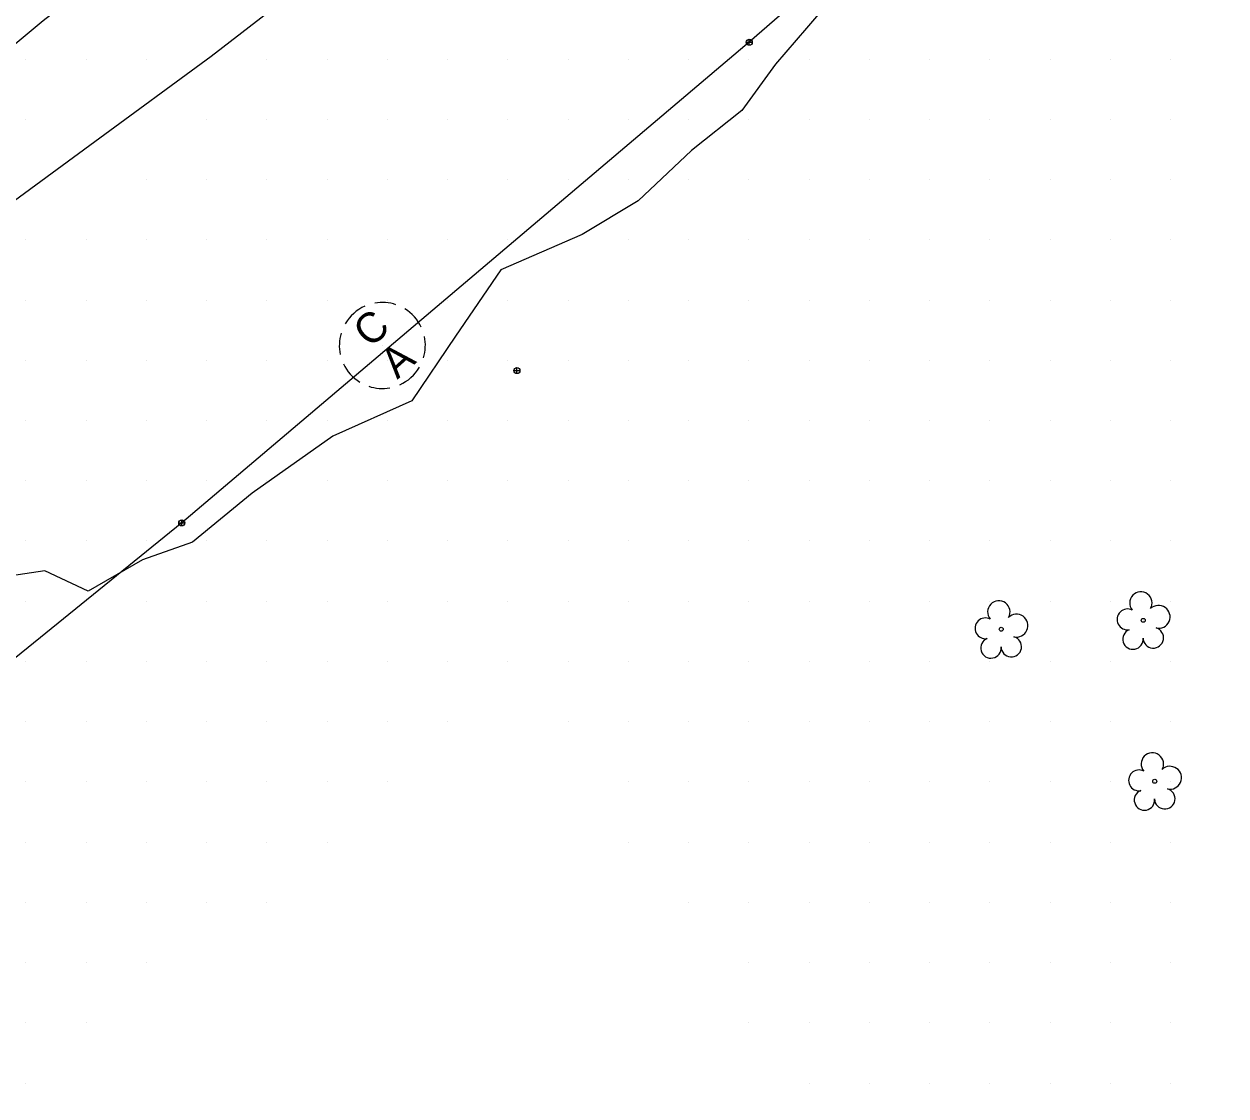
# Model space of a CAD drawing. Extents: x 1548934 to 1561348, y 809680 to 824075.
# Drawn here: x 1551639.7 to 1551839.2, y 810277.8 to 810455.8 of the extents above; entities that cross this region are included whole.
import ezdxf

# ---------------------------------------------------------------- set-up
doc = ezdxf.new("R2010")
doc.units = 0
for name, color, linetype in [('Default', 7, 'Continuous'), ('Exist DTM QL2 LIDAR Elevation Point', 7, 'Continuous'), ('Exist Right of Way Control of Access CA Symbol CELL', 7, 'Continuous'), ('Exist Vegetation Tree CELL', 7, 'Continuous'), ('Exist Vegetation Woods Line', 7, 'Continuous'), ('P_RDY_Dimension_Text', 7, 'Continuous'), ('PH Exist DTM Breakline', 7, 'Continuous')]:
    doc.layers.add(name, color=color, linetype=linetype)

# ---------------------------------------------------------------- blocks, each defined once
blk = doc.blocks.new('SurveyPointCell')
at = {"layer": 'Default'}
for p, q in [((-0.5, 0), (0.5, 0)), ((0, -0.5), (0, 0.5))]:
    blk.add_line(p, q, dxfattribs=at)
blk.add_circle((0, 0), 0.5, dxfattribs=at)

msp = doc.modelspace()

# ---------------------------------------------------------------- linework, layer by layer
at = {"layer": 'Exist DTM QL2 LIDAR Elevation Point'}
for p, q in [((1551639.99, 810449.97), (1551639.99, 810449.97)), ((1551649.99, 810449.97), (1551649.99, 810449.97)), ((1551659.99, 810449.97), (1551659.99, 810449.97)), ((1551679.99, 810449.97), (1551679.99, 810449.97)), ((1551689.99, 810449.97), (1551689.99, 810449.97)), ((1551699.99, 810449.97), (1551699.99, 810449.97)), ((1551710, 810449.97), (1551710, 810449.97)), ((1551720, 810449.97), (1551720, 810449.97)), ((1551730, 810449.97), (1551730, 810449.97)), ((1551740, 810449.97), (1551740, 810449.97)), ((1551750, 810449.97), (1551750, 810449.97)), ((1551760, 810449.97), (1551760, 810449.97)), ((1551770, 810449.97), (1551770, 810449.97)), ((1551780, 810449.97), (1551780, 810449.97)), ((1551790, 810449.97), (1551790, 810449.97)), ((1551800, 810449.97), (1551800, 810449.97)), ((1551810, 810449.97), (1551810, 810449.97)), ((1551820, 810449.97), (1551820, 810449.97)), ((1551830.01, 810449.97), (1551830.01, 810449.97)), ((1551639.99, 810439.97), (1551639.99, 810439.97)), ((1551669.99, 810439.97), (1551669.99, 810439.97)), ((1551679.99, 810439.97), (1551679.99, 810439.97)), ((1551689.99, 810439.97), (1551689.99, 810439.97)), ((1551699.99, 810439.97), (1551699.99, 810439.97)), ((1551710, 810439.97), (1551710, 810439.97)), ((1551720, 810439.97), (1551720, 810439.97)), ((1551730, 810439.97), (1551730, 810439.97)), ((1551740, 810439.97), (1551740, 810439.97)), ((1551750, 810439.97), (1551750, 810439.97)), ((1551760, 810439.97), (1551760, 810439.97)), ((1551770, 810439.97), (1551770, 810439.97)), ((1551780, 810439.97), (1551780, 810439.97)), ((1551790, 810439.97), (1551790, 810439.97)), ((1551800, 810439.97), (1551800, 810439.97)), ((1551810, 810439.97), (1551810, 810439.97)), ((1551820, 810439.97), (1551820, 810439.97)), ((1551830.01, 810439.97), (1551830.01, 810439.97)), ((1551659.99, 810429.97), (1551659.99, 810429.97)), ((1551669.99, 810429.97), (1551669.99, 810429.97)), ((1551679.99, 810429.97), (1551679.99, 810429.97)), ((1551689.99, 810429.97), (1551689.99, 810429.97)), ((1551699.99, 810429.97), (1551699.99, 810429.97)), ((1551710, 810429.97), (1551710, 810429.97)), ((1551720, 810429.97), (1551720, 810429.97)), ((1551730, 810429.97), (1551730, 810429.97)), ((1551740, 810429.97), (1551740, 810429.97)), ((1551750, 810429.97), (1551750, 810429.97)), ((1551760, 810429.97), (1551760, 810429.97)), ((1551770, 810429.97), (1551770, 810429.97)), ((1551780, 810429.97), (1551780, 810429.97)), ((1551790, 810429.97), (1551790, 810429.97)), ((1551800, 810429.97), (1551800, 810429.97)), ((1551810, 810429.97), (1551810, 810429.97)), ((1551820, 810429.97), (1551820, 810429.97)), ((1551830.01, 810429.97), (1551830.01, 810429.97)), ((1551639.99, 810419.96), (1551639.99, 810419.96)), ((1551649.99, 810419.96), (1551649.99, 810419.96)), ((1551659.99, 810419.96), (1551659.99, 810419.96)), ((1551669.99, 810419.96), (1551669.99, 810419.96)), ((1551679.99, 810419.96), (1551679.99, 810419.96)), ((1551689.99, 810419.96), (1551689.99, 810419.96)), ((1551699.99, 810419.96), (1551699.99, 810419.96)), ((1551710, 810419.96), (1551710, 810419.96)), ((1551720, 810419.96), (1551720, 810419.96)), ((1551730, 810419.96), (1551730, 810419.96)), ((1551740, 810419.96), (1551740, 810419.96)), ((1551750, 810419.96), (1551750, 810419.96)), ((1551760, 810419.96), (1551760, 810419.96)), ((1551770, 810419.96), (1551770, 810419.96)), ((1551780, 810419.96), (1551780, 810419.96)), ((1551790, 810419.96), (1551790, 810419.96)), ((1551800, 810419.96), (1551800, 810419.96)), ((1551810, 810419.96), (1551810, 810419.96)), ((1551820, 810419.96), (1551820, 810419.96)), ((1551830.01, 810419.96), (1551830.01, 810419.96)), ((1551639.99, 810409.96), (1551639.99, 810409.96)), ((1551649.99, 810409.96), (1551649.99, 810409.96)), ((1551659.99, 810409.96), (1551659.99, 810409.96)), ((1551669.99, 810409.96), (1551669.99, 810409.96)), ((1551679.99, 810409.96), (1551679.99, 810409.96)), ((1551689.99, 810409.96), (1551689.99, 810409.96)), ((1551699.99, 810409.96), (1551699.99, 810409.96)), ((1551710, 810409.96), (1551710, 810409.96)), ((1551720, 810409.96), (1551720, 810409.96)), ((1551730, 810409.96), (1551730, 810409.96)), ((1551740, 810409.96), (1551740, 810409.96)), ((1551750, 810409.96), (1551750, 810409.96)), ((1551760, 810409.96), (1551760, 810409.96)), ((1551770, 810409.96), (1551770, 810409.96)), ((1551780, 810409.96), (1551780, 810409.96)), ((1551790, 810409.96), (1551790, 810409.96)), ((1551800, 810409.96), (1551800, 810409.96)), ((1551810, 810409.96), (1551810, 810409.96)), ((1551820, 810409.96), (1551820, 810409.96)), ((1551830.01, 810409.96), (1551830.01, 810409.96)), ((1551639.99, 810399.96), (1551639.99, 810399.96)), ((1551649.99, 810399.96), (1551649.99, 810399.96)), ((1551659.99, 810399.96), (1551659.99, 810399.96)), ((1551669.99, 810399.96), (1551669.99, 810399.96)), ((1551679.99, 810399.96), (1551679.99, 810399.96)), ((1551689.99, 810399.96), (1551689.99, 810399.96)), ((1551699.99, 810399.96), (1551699.99, 810399.96)), ((1551710, 810399.96), (1551710, 810399.96)), ((1551720, 810399.96), (1551720, 810399.96)), ((1551730, 810399.96), (1551730, 810399.96)), ((1551740, 810399.96), (1551740, 810399.96)), ((1551750, 810399.96), (1551750, 810399.96)), ((1551760, 810399.96), (1551760, 810399.96)), ((1551770, 810399.96), (1551770, 810399.96)), ((1551780, 810399.96), (1551780, 810399.96)), ((1551790, 810399.96), (1551790, 810399.96)), ((1551800, 810399.96), (1551800, 810399.96)), ((1551810, 810399.96), (1551810, 810399.96)), ((1551820, 810399.96), (1551820, 810399.96)), ((1551830.01, 810399.96), (1551830.01, 810399.96)), ((1551639.99, 810389.96), (1551639.99, 810389.96)), ((1551649.99, 810389.96), (1551649.99, 810389.96)), ((1551659.99, 810389.96), (1551659.99, 810389.96)), ((1551669.99, 810389.96), (1551669.99, 810389.96)), ((1551679.99, 810389.96), (1551679.99, 810389.96)), ((1551689.99, 810389.96), (1551689.99, 810389.96)), ((1551699.99, 810389.96), (1551699.99, 810389.96)), ((1551710, 810389.96), (1551710, 810389.96)), ((1551720, 810389.96), (1551720, 810389.96)), ((1551730, 810389.96), (1551730, 810389.96)), ((1551740, 810389.96), (1551740, 810389.96)), ((1551750, 810389.96), (1551750, 810389.96)), ((1551760, 810389.96), (1551760, 810389.96)), ((1551770, 810389.96), (1551770, 810389.96)), ((1551780, 810389.96), (1551780, 810389.96)), ((1551790, 810389.96), (1551790, 810389.96)), ((1551800, 810389.96), (1551800, 810389.96)), ((1551810, 810389.96), (1551810, 810389.96)), ((1551820, 810389.96), (1551820, 810389.96)), ((1551830.01, 810389.96), (1551830.01, 810389.96)), ((1551639.99, 810379.96), (1551639.99, 810379.96)), ((1551649.99, 810379.96), (1551649.99, 810379.96)), ((1551659.99, 810379.96), (1551659.99, 810379.96)), ((1551669.99, 810379.96), (1551669.99, 810379.96)), ((1551679.99, 810379.96), (1551679.99, 810379.96)), ((1551689.99, 810379.96), (1551689.99, 810379.96)), ((1551699.99, 810379.96), (1551699.99, 810379.96)), ((1551710, 810379.96), (1551710, 810379.96)), ((1551720, 810379.96), (1551720, 810379.96)), ((1551730, 810379.96), (1551730, 810379.96)), ((1551740, 810379.96), (1551740, 810379.96)), ((1551750, 810379.96), (1551750, 810379.96)), ((1551760, 810379.96), (1551760, 810379.96)), ((1551770, 810379.96), (1551770, 810379.96)), ((1551780, 810379.96), (1551780, 810379.96)), ((1551790, 810379.96), (1551790, 810379.96)), ((1551800, 810379.96), (1551800, 810379.96)), ((1551810, 810379.96), (1551810, 810379.96)), ((1551820, 810379.96), (1551820, 810379.96)), ((1551830.01, 810379.96), (1551830.01, 810379.96)), ((1551639.99, 810369.96), (1551639.99, 810369.96)), ((1551649.99, 810369.96), (1551649.99, 810369.96)), ((1551659.99, 810369.96), (1551659.99, 810369.96)), ((1551669.99, 810369.96), (1551669.99, 810369.96)), ((1551679.99, 810369.96), (1551679.99, 810369.96)), ((1551689.99, 810369.96), (1551689.99, 810369.96)), ((1551699.99, 810369.96), (1551699.99, 810369.96)), ((1551710, 810369.96), (1551710, 810369.96)), ((1551720, 810369.96), (1551720, 810369.96)), ((1551730, 810369.96), (1551730, 810369.96)), ((1551740, 810369.96), (1551740, 810369.96)), ((1551750, 810369.96), (1551750, 810369.96)), ((1551760, 810369.96), (1551760, 810369.96)), ((1551770, 810369.96), (1551770, 810369.96)), ((1551780, 810369.96), (1551780, 810369.96)), ((1551790, 810369.96), (1551790, 810369.96)), ((1551800, 810369.96), (1551800, 810369.96)), ((1551810, 810369.96), (1551810, 810369.96)), ((1551820, 810369.96), (1551820, 810369.96)), ((1551830.01, 810369.96), (1551830.01, 810369.96)), ((1551639.99, 810359.96), (1551639.99, 810359.96)), ((1551649.99, 810359.96), (1551649.99, 810359.96)), ((1551659.99, 810359.96), (1551659.99, 810359.96)), ((1551669.99, 810359.96), (1551669.99, 810359.96)), ((1551679.99, 810359.96), (1551679.99, 810359.96)), ((1551689.99, 810359.96), (1551689.99, 810359.96)), ((1551699.99, 810359.96), (1551699.99, 810359.96)), ((1551710, 810359.96), (1551710, 810359.96)), ((1551720, 810359.96), (1551720, 810359.96)), ((1551730, 810359.96), (1551730, 810359.96)), ((1551740, 810359.96), (1551740, 810359.96)), ((1551750, 810359.96), (1551750, 810359.96)), ((1551760, 810359.96), (1551760, 810359.96)), ((1551770, 810359.96), (1551770, 810359.96)), ((1551780, 810359.96), (1551780, 810359.96)), ((1551790, 810359.96), (1551790, 810359.96)), ((1551800, 810359.96), (1551800, 810359.96)), ((1551810, 810359.96), (1551810, 810359.96)), ((1551820, 810359.96), (1551820, 810359.96)), ((1551830.01, 810359.96), (1551830.01, 810359.96)), ((1551639.99, 810349.96), (1551639.99, 810349.96)), ((1551649.99, 810349.96), (1551649.99, 810349.96)), ((1551659.99, 810349.96), (1551659.99, 810349.96)), ((1551669.99, 810349.96), (1551669.99, 810349.96)), ((1551679.99, 810349.96), (1551679.99, 810349.96)), ((1551689.99, 810349.96), (1551689.99, 810349.96)), ((1551699.99, 810349.96), (1551699.99, 810349.96)), ((1551710, 810349.96), (1551710, 810349.96)), ((1551720, 810349.96), (1551720, 810349.96)), ((1551730, 810349.96), (1551730, 810349.96)), ((1551740, 810349.96), (1551740, 810349.96)), ((1551750, 810349.96), (1551750, 810349.96)), ((1551760, 810349.96), (1551760, 810349.96)), ((1551770, 810349.96), (1551770, 810349.96)), ((1551780, 810349.96), (1551780, 810349.96)), ((1551790, 810349.96), (1551790, 810349.96)), ((1551800, 810349.96), (1551800, 810349.96)), ((1551810, 810349.96), (1551810, 810349.96)), ((1551820, 810349.96), (1551820, 810349.96)), ((1551830.01, 810349.96), (1551830.01, 810349.96)), ((1551639.99, 810339.96), (1551639.99, 810339.96)), ((1551649.99, 810339.96), (1551649.99, 810339.96)), ((1551659.99, 810339.96), (1551659.99, 810339.96)), ((1551669.99, 810339.96), (1551669.99, 810339.96)), ((1551679.99, 810339.96), (1551679.99, 810339.96)), ((1551689.99, 810339.96), (1551689.99, 810339.96)), ((1551699.99, 810339.96), (1551699.99, 810339.96)), ((1551710, 810339.96), (1551710, 810339.96)), ((1551730, 810339.96), (1551730, 810339.96)), ((1551740, 810339.96), (1551740, 810339.96)), ((1551750, 810339.96), (1551750, 810339.96)), ((1551760, 810339.96), (1551760, 810339.96)), ((1551770, 810339.96), (1551770, 810339.96)), ((1551780, 810339.96), (1551780, 810339.96)), ((1551790, 810339.96), (1551790, 810339.96)), ((1551800, 810339.96), (1551800, 810339.96)), ((1551810, 810339.96), (1551810, 810339.96)), ((1551820, 810339.96), (1551820, 810339.96)), ((1551830.01, 810339.96), (1551830.01, 810339.96)), ((1551639.99, 810329.96), (1551639.99, 810329.96)), ((1551649.99, 810329.96), (1551649.99, 810329.96)), ((1551659.99, 810329.96), (1551659.99, 810329.96)), ((1551669.99, 810329.96), (1551669.99, 810329.96)), ((1551679.99, 810329.96), (1551679.99, 810329.96)), ((1551689.99, 810329.96), (1551689.99, 810329.96)), ((1551699.99, 810329.96), (1551699.99, 810329.96)), ((1551740, 810329.96), (1551740, 810329.96)), ((1551750, 810329.96), (1551750, 810329.96)), ((1551760, 810329.96), (1551760, 810329.96)), ((1551770, 810329.96), (1551770, 810329.96)), ((1551780, 810329.96), (1551780, 810329.96)), ((1551790, 810329.96), (1551790, 810329.96)), ((1551800, 810329.96), (1551800, 810329.96)), ((1551810, 810329.96), (1551810, 810329.96)), ((1551820, 810329.96), (1551820, 810329.96)), ((1551830.01, 810329.96), (1551830.01, 810329.96)), ((1551639.99, 810319.96), (1551639.99, 810319.96)), ((1551649.99, 810319.96), (1551649.99, 810319.96)), ((1551659.99, 810319.96), (1551659.99, 810319.96)), ((1551669.99, 810319.96), (1551669.99, 810319.96)), ((1551679.99, 810319.96), (1551679.99, 810319.96)), ((1551689.99, 810319.96), (1551689.99, 810319.96)), ((1551740, 810319.96), (1551740, 810319.96)), ((1551750, 810319.96), (1551750, 810319.96)), ((1551760, 810319.96), (1551760, 810319.96)), ((1551770, 810319.96), (1551770, 810319.96)), ((1551780, 810319.96), (1551780, 810319.96)), ((1551790, 810319.96), (1551790, 810319.96)), ((1551800, 810319.96), (1551800, 810319.96)), ((1551810, 810319.96), (1551810, 810319.96)), ((1551820, 810319.96), (1551820, 810319.96)), ((1551830.01, 810319.96), (1551830.01, 810319.96)), ((1551639.99, 810309.96), (1551639.99, 810309.96)), ((1551649.99, 810309.96), (1551649.99, 810309.96)), ((1551659.99, 810309.96), (1551659.99, 810309.96)), ((1551669.99, 810309.96), (1551669.99, 810309.96)), ((1551679.99, 810309.96), (1551679.99, 810309.96)), ((1551750, 810309.96), (1551750, 810309.96)), ((1551760, 810309.96), (1551760, 810309.96)), ((1551770, 810309.96), (1551770, 810309.96)), ((1551780, 810309.96), (1551780, 810309.96)), ((1551790, 810309.96), (1551790, 810309.96)), ((1551800, 810309.96), (1551800, 810309.96)), ((1551810, 810309.96), (1551810, 810309.96)), ((1551820, 810309.96), (1551820, 810309.96)), ((1551830.01, 810309.96), (1551830.01, 810309.96)), ((1551639.99, 810299.96), (1551639.99, 810299.96)), ((1551649.99, 810299.96), (1551649.99, 810299.96)), ((1551659.99, 810299.96), (1551659.99, 810299.96)), ((1551760, 810299.96), (1551760, 810299.96)), ((1551770, 810299.96), (1551770, 810299.96)), ((1551780, 810299.96), (1551780, 810299.96)), ((1551790, 810299.96), (1551790, 810299.96)), ((1551800, 810299.96), (1551800, 810299.96)), ((1551810, 810299.96), (1551810, 810299.96)), ((1551820, 810299.96), (1551820, 810299.96)), ((1551830.01, 810299.96), (1551830.01, 810299.96)), ((1551639.99, 810289.95), (1551639.99, 810289.95)), ((1551649.99, 810289.95), (1551649.99, 810289.95)), ((1551760, 810289.95), (1551760, 810289.95)), ((1551770, 810289.95), (1551770, 810289.95)), ((1551780, 810289.95), (1551780, 810289.95)), ((1551790, 810289.95), (1551790, 810289.95)), ((1551800, 810289.95), (1551800, 810289.95)), ((1551810, 810289.95), (1551810, 810289.95)), ((1551820, 810289.95), (1551820, 810289.95)), ((1551830.01, 810289.95), (1551830.01, 810289.95)), ((1551639.99, 810279.95), (1551639.99, 810279.95)), ((1551770, 810279.95), (1551770, 810279.95)), ((1551780, 810279.95), (1551780, 810279.95)), ((1551790, 810279.95), (1551790, 810279.95)), ((1551800, 810279.95), (1551800, 810279.95)), ((1551810, 810279.95), (1551810, 810279.95)), ((1551820, 810279.95), (1551820, 810279.95)), ((1551830.01, 810279.95), (1551830.01, 810279.95))]:
    msp.add_line(p, q, dxfattribs=at)
at = {"layer": 'Exist Right of Way Control of Access CA Symbol CELL'}
msp.add_line((1551699.17, 810402.41), (1551699.17, 810402.41), dxfattribs=at)
for start, end in [(71.5349, 100.1228), (113.9162, 149.5284), (25.1429, 58.3017), (163.3219, 191.9097), (343.3219, 11.9097), (205.1429, 238.3017), (293.9162, 329.5284), (251.5349, 280.1228)]:
    msp.add_arc((1551699.17, 810402.41), 7.14, start, end, dxfattribs=at)
at = {"layer": 'Exist Vegetation Tree CELL'}
for p, q in [((1551801.89, 810355.3), (1551801.89, 810355.3)), ((1551825.47, 810356.77), (1551825.47, 810356.77)), ((1551827.37, 810330.05), (1551827.37, 810330.05))]:
    msp.add_line(p, q, dxfattribs=at)
for centre in [(1551801.89, 810355.3), (1551825.47, 810356.77), (1551827.37, 810330.05)]:
    msp.add_circle(centre, 0.326, dxfattribs=at)
for centre, radius, start, end in [((1551825.08, 810359.65), 1.86, 330.1651, 219.7134), ((1551801.5, 810358.17), 1.86, 330.1651, 219.7134), ((1551804.43, 810355.89), 1.9, 257.1011, 134.1999), ((1551822.86, 810356.93), 1.73, 62.6636, 279.3457), ((1551828.02, 810357.36), 1.9, 257.1011, 134.1999), ((1551799.28, 810355.45), 1.73, 62.6636, 279.3457), ((1551827.14, 810353.87), 1.7, 181.2822, 74.56), ((1551800.18, 810352.18), 1.69, 111.5671, 6.231), ((1551803.56, 810352.4), 1.7, 181.2822, 74.56), ((1551823.76, 810353.65), 1.69, 111.5671, 6.231), ((1551826.99, 810332.92), 1.86, 330.1651, 219.7134), ((1551824.76, 810330.2), 1.73, 62.6636, 279.3457), ((1551829.92, 810330.64), 1.9, 257.1011, 134.1999), ((1551825.67, 810326.93), 1.69, 111.5671, 6.231), ((1551829.04, 810327.15), 1.7, 181.2822, 74.56)]:
    msp.add_arc(centre, radius, start, end, dxfattribs=at)
at = {"layer": 'Exist Vegetation Woods Line'}
for points in [[(1551844.62, 810532.53), (1551836.39, 810523.01), (1551831.5, 810514.84), (1551828.62, 810509.31), (1551821.73, 810502.86), (1551813.45, 810493.49), (1551808.75, 810486.26), (1551802.88, 810477.92), (1551794.7, 810471.19), (1551782.73, 810465.36), (1551774.21, 810460.58), (1551769.57, 810455.11), (1551764.42, 810449.11), (1551758.85, 810441.4), (1551750.46, 810434.77), (1551741.65, 810426.42), (1551732.36, 810420.85), (1551718.85, 810414.99), (1551711.33, 810403.98), (1551704.06, 810393.24)], [(1551471.33, 810309.76), (1551496.19, 810327.35), (1551520.55, 810342.93), (1551538.1, 810357.1), (1551563.58, 810380.42), (1551579.64, 810396.97), (1551595.16, 810410.86), (1551619.57, 810437), (1551642.9, 810456.37), (1551671.93, 810478.9)], [(1551704.06, 810393.24), (1551690.95, 810387.37), (1551677.59, 810377.87), (1551667.65, 810369.78), (1551659.37, 810366.8), (1551650.36, 810361.59), (1551643.13, 810364.98), (1551628.69, 810362.84), (1551634.09, 810350.14), (1551632.23, 810346.13), (1551621.54, 810338.68), (1551609.38, 810331.29), (1551587.67, 810308.27), (1551572.84, 810295.21), (1551556.27, 810282.23), (1551533.93, 810267.67), (1551517.37, 810252.68)]]:
    msp.add_lwpolyline(points, dxfattribs=at)
at = {"layer": 'P_RDY_Dimension_Text'}
msp.add_lwpolyline([(1551859.71, 810539.41), (1551760.08, 810452.75), (1551665.88, 810372.94), (1551515.48, 810250.92)], dxfattribs=at)
at = {"layer": 'PH Exist DTM Breakline'}
msp.add_lwpolyline([(1551477.62, 810298.3), (1551490.74, 810306.41), (1551501.52, 810315.49), (1551512.44, 810323.02), (1551523.43, 810332.94), (1551538.32, 810346.42), (1551548.49, 810354.56), (1551561.25, 810365.28), (1551570.99, 810375.62), (1551593.88, 810390.41), (1551601.53, 810396.72), (1551614.89, 810407.77), (1551625.58, 810416.03), (1551632.63, 810422.48), (1551651.47, 810436.29), (1551670.78, 810450.45), (1551699.84, 810472.96)], dxfattribs=at)

# ---------------------------------------------------------------- block references
at = {"layer": 'Default'}
for p in [(1551760.08, 810452.75), (1551721.52, 810398.24), (1551665.88, 810372.94)]:
    msp.add_blockref('SurveyPointCell', p, dxfattribs=at)

# ---------------------------------------------------------------- texts
at = {"layer": 'Exist Right of Way Control of Access CA Symbol CELL'}
for s, p in [('C', (1551697.15, 810401.86)), ('A', (1551701.66, 810396.7))]:
    msp.add_text(s, height=5, rotation=41.7223, dxfattribs=at).set_placement(p)

doc.saveas('drawing.dxf')
